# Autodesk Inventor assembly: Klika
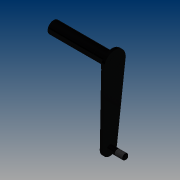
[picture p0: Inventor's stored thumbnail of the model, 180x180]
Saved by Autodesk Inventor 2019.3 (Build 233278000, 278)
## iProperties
Created: 2019-02
Part Number: Klika
Material: Všeobecné
Document SubType Name: Assembly
Designer: B-hon
Author: B-hon
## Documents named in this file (5)
- C:\Users\B-hon\OneDrive\Plocha\Bakalářka22\Klika\Klika.iam
- C:\Users\B-hon\OneDrive\Plocha\Bakalářka22\Klika\Hřídel.ipt
- C:\Users\B-hon\OneDrive\Plocha\Bakalářka22\Klika\Rameno kliky.ipt
- C:\Users\B-hon\OneDrive\Plocha\Bakalářka22\Klika\Čep ojnice.ipt
- C:\Users\B-hon\OneDrive\Plocha\Bakalářka22\Klika\Výztuha ramene.ipt
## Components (4 placed, 4 different names)
1. Hřídel:1 — Vložit:1, Tečnost:1
2. Rameno kliky:1 — Vložit:1, Vložit:2, Proti sobě:1, Proti sobě:2
3. Čep ojnice:1 — Vložit:2
4. Výztuha ramene:1 — Proti sobě:1, Proti sobě:2, Tečnost:1
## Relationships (5: Insert 2, Mate 2, Tangent 1)
- Vložit:1 [Insert]: Hřídel:1 ↔ Rameno kliky:1
- Vložit:2 [Insert]: Rameno kliky:1 ↔ Čep ojnice:1
- Proti sobě:1 [Mate]: Rameno kliky:1 ↔ Výztuha ramene:1
- Proti sobě:2 [Mate]: Rameno kliky:1 ↔ Výztuha ramene:1
- Tečnost:1 [Tangent]: Hřídel:1 ↔ Výztuha ramene:1
## Named parameters: sa_0 = 0, sa_1 = -276998.50181 mm, sa_2 = 23576.047 mm
